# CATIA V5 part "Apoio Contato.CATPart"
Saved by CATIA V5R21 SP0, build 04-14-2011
Part number: Apoio Contato
Definition: Apoio Contato
Nomenclature: Apoio Contato
Source: Unknown
Bounding box of the stored display mesh (mm): x -0.9 to 0.9, y -0.02 to 0.12, z -0.9 to 0.9
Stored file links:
  C:\Users\beatr\OneDrive\Documents\UNB\2026_1\Pi1\Componentes eletronicos\Apoio Contato.CATPart
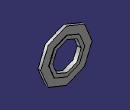
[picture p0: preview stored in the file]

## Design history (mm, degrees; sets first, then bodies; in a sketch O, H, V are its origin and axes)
Body1 "Sólido1" (main body)
  Solid1: solid without history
